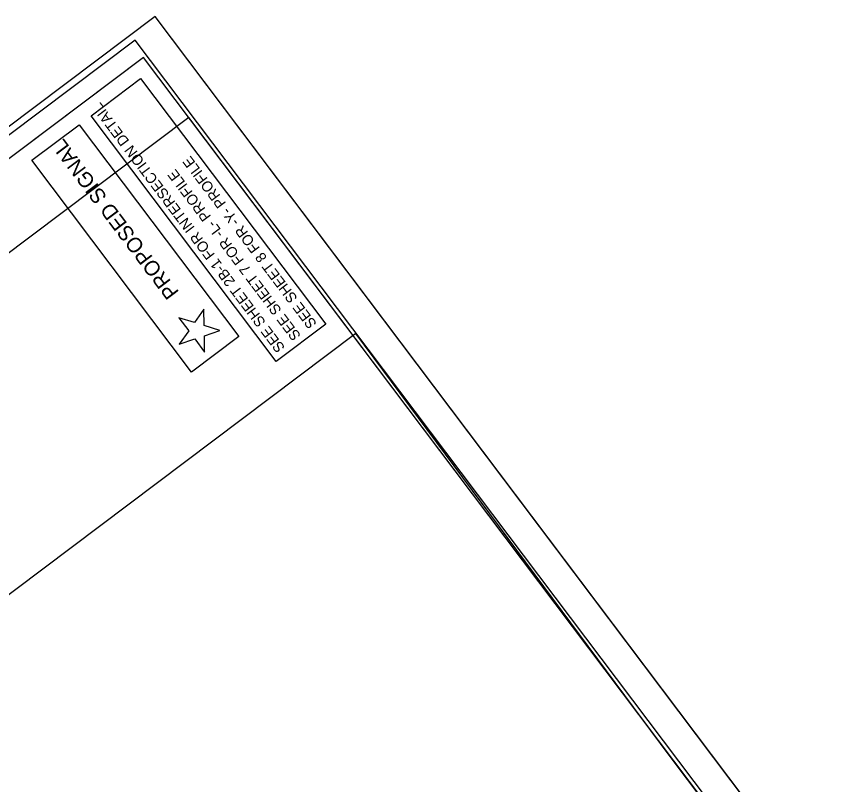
# Model space of a CAD drawing. Extents: x 1262337 to 1264328, y 775525 to 777528.
# Drawn here: x 1263223 to 1263776, y 777017 to 777528 of the extents above; entities that cross this region are included whole.
import ezdxf

# ---------------------------------------------------------------- set-up
doc = ezdxf.new("R2010")
doc.units = 0
for name, color, linetype in [('Sheet Clip Boundary CELL', 7, 'Continuous'), ('Sheet Cutting Line CELL', 7, 'Continuous'), ('Sheet Layout Plan Border', 7, 'Continuous'), ('Sheet North Arrow CELL', 7, 'Continuous'), ('Sheet Plan CELL', 7, 'Continuous'), ('Sheet Plan Layout CELL', 7, 'Continuous'), ('Sheet Plot Border Inside CELL', 7, 'Continuous'), ('Sheet Plot Border Outside CELL', 7, 'Continuous'), ('Sheet Sticker Incomplete CELL', 7, 'Continuous'), ('Sheet Sticker Preliminary CELL', 7, 'Continuous')]:
    doc.layers.add(name, color=color, linetype=linetype)

msp = doc.modelspace()

# ---------------------------------------------------------------- linework, layer by layer
at = {"layer": 'Sheet Clip Boundary CELL'}
msp.add_lwpolyline([(1263888.49, 776271.07), (1264108.83, 776437.03), (1263657.31, 777036.5), (1263449.04, 777317.16), (1262881.72, 776889.85), (1262608.34, 776683.94), (1263270.12, 775805.31)], close=True, dxfattribs=at)
at = {"layer": 'Sheet Cutting Line CELL'}
msp.add_line((1264328.45, 776183.46), (1263315.59, 777528.19), dxfattribs=at)
at = {"layer": 'Sheet Layout Plan Border'}
msp.add_lwpolyline([(1264180.22, 776342.84), (1263337.92, 777461.13), (1262668.14, 776956.65), (1262782.01, 776805.47), (1262613.08, 776678.23), (1263341.52, 775711.12)], close=True, dxfattribs=at)
at = {"layer": 'Sheet Plan CELL'}
msp.add_lwpolyline([(1262469.12, 776869.36), (1263371.6, 775671.18), (1264210.31, 776302.91), (1263307.84, 777501.07)], close=True, dxfattribs=at)
at = {"layer": 'Sheet Plan Layout CELL'}
msp.add_lwpolyline([(1263371.64, 775671.18), (1264210.31, 776302.91), (1263307.85, 777501.06), (1262638.07, 776996.57), (1262782.01, 776805.47), (1262613.08, 776678.23)], close=True, dxfattribs=at)
at = {"layer": 'Sheet Plot Border Inside CELL'}
msp.add_lwpolyline([(1264304.66, 776181.82), (1263302.32, 777512.55), (1262459.63, 776877.83), (1263461.96, 775547.09)], close=True, dxfattribs=at)
at = {"layer": 'Sheet Plot Border Outside CELL'}
for points in [[(1264328.45, 776183.46), (1263315.59, 777528.19), (1262440.94, 776869.39), (1263453.8, 775524.67)], [(1263396.07, 777298.67), (1263272.88, 777462.22), (1263305.87, 777487.06), (1263429.05, 777323.51)]]:
    msp.add_lwpolyline(points, close=True, dxfattribs=at)
at = {"layer": 'Sheet Sticker Incomplete CELL'}
msp.add_lwpolyline([(1263339.7, 777291.5), (1263233.47, 777432.53), (1263264.89, 777456.2), (1263371.12, 777315.17)], close=True, dxfattribs=at)
at = {"layer": 'Sheet Sticker Preliminary CELL'}
msp.add_lwpolyline([(1263341.88, 777313.61), (1263348.42, 777304.92), (1263348.23, 777315.8), (1263358.55, 777319.35), (1263348.12, 777322.54), (1263347.92, 777333.43), (1263341.68, 777324.51), (1263331.26, 777327.7), (1263337.82, 777319), (1263331.57, 777310.06), (1263341.88, 777313.61)], dxfattribs=at)

# ---------------------------------------------------------------- texts
at = {"layer": 'Sheet North Arrow CELL'}
msp.add_text('PROPOSED SIGNAL', height=10, rotation=126.9874, dxfattribs=at).set_placement((1263331.76, 777344.77))
at = {"layer": 'Sheet Plot Border Outside CELL'}
for s, p in [('SEE SHEET 2B-1 FOR INTERSECTION DETAIL', (1263402.19, 777307.84)), ('SEE SHEET 8 FOR -Y- PROFILE', (1263423.36, 777323.78)), ('SEE SHEET 7 FOR -L- PROFILE', (1263412.77, 777315.81))]:
    msp.add_text(s, height=7, rotation=126.9874, dxfattribs=at).set_placement(p)

doc.saveas('drawing.dxf')
